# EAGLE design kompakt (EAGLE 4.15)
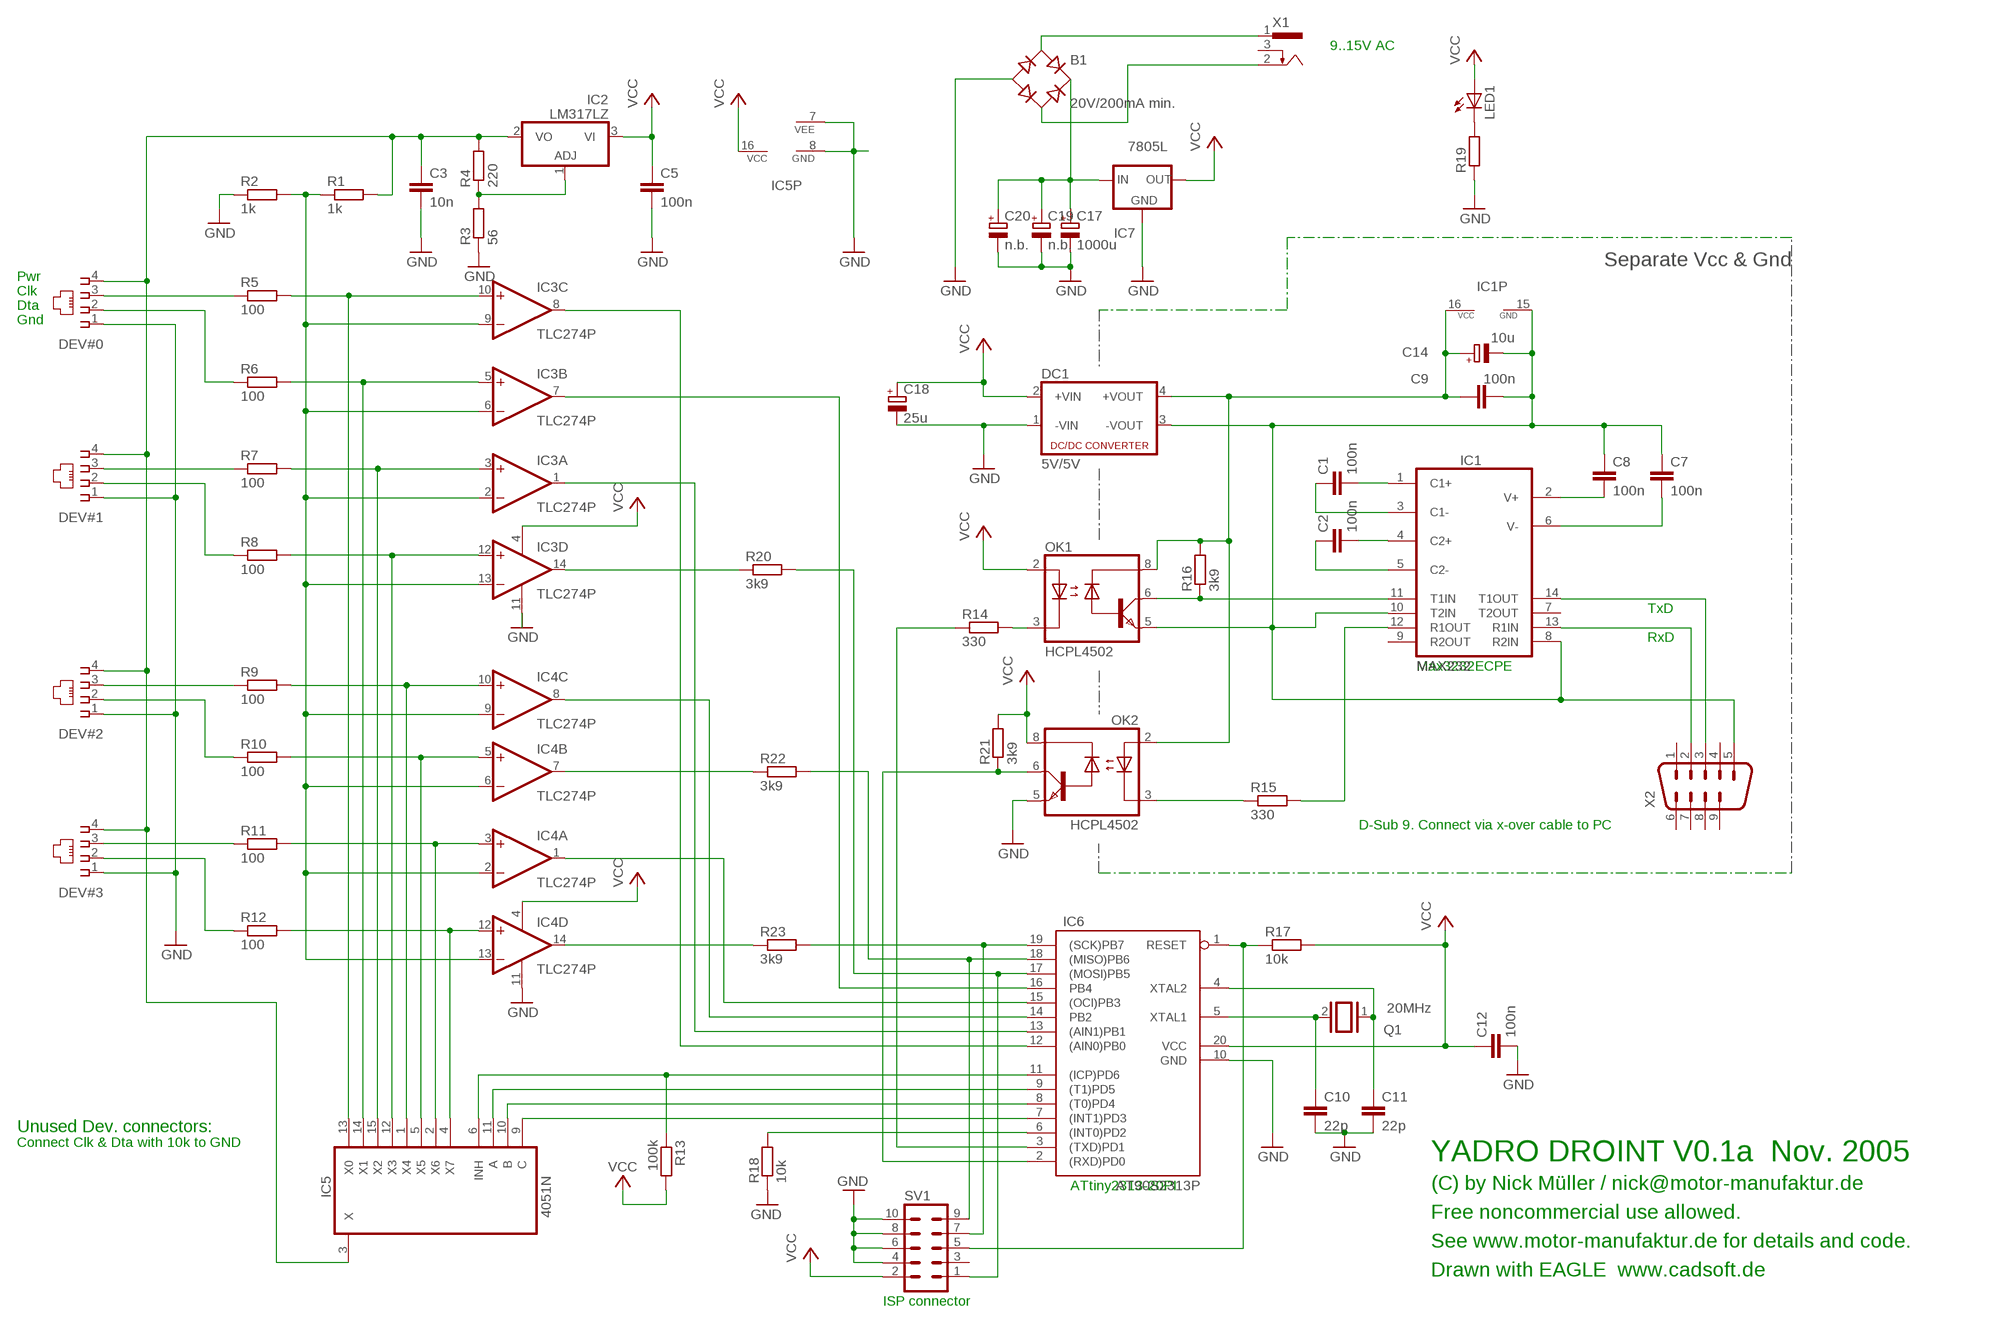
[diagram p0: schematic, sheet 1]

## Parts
B1  20V/200mA min.  RB1A  [RB1A]
C1  100n  C-EU050-030X075  [C050-030X075]
C2  100n  C-EU050-030X075  [C050-030X075]
C3  10n  C-EU025-025X050  [C025-025X050]
C5  100n  C-EU050-030X075  [C050-030X075]
C7  100n  C-EU050-030X075  [C050-030X075]
C8  100n  C-EU050-030X075  [C050-030X075]
C9  100n  C-EU050-030X075  [C050-030X075]
C10  22p  C-EU025-025X050  [C025-025X050]
C11  22p  C-EU025-025X050  [C025-025X050]
C12  100n  C-EU050-030X075  [C050-030X075]
C14  10u  CPOL-EUE5-5  [E5-5]
C17  1000u  CPOL-EUE5-13  [E5-13]
C18  25u  CPOL-EUE5-8.5  [E5-8,5]
C19  n.b.  CPOL-EUE5-10.5  [E5-10,5]
C20  n.b.  CPOL-EUE5-10.5  [E5-10,5]
DC1  5V/5V  NME  [NME]
DEV#0  215876-6  [215876-6]
DEV#1  215876-6  [215876-6]
DEV#2  215876-6  [215876-6]
DEV#3  215876-6  [215876-6]
IC1  MAX232  [DIL16]
IC2  LM317LZ  [TO92]
IC3  TLC274P  [DIL14]
IC4  TLC274P  [DIL14]
IC5  4051N  [DIL16]
IC6  AT90S2313P  [DIL20]
IC7  7805L  78XXL  [78XXL]
LED1  LED3MM  [LED3MM]
OK1  HCPL4502  [DIL08]
OK2  HCPL4502  [DIL08]
Q1  20MHz  XTAL/S  [QS]
R1  1k  R-EU_0207/7  [0207/7]
R2  1k  R-EU_0207/7  [0207/7]
R3  56  R-EU_0207/7  [0207/7]
R4  220  R-EU_0207/7  [0207/7]
R5  100  R-EU_0207/7  [0207/7]
R6  100  R-EU_0207/7  [0207/7]
R7  100  R-EU_0207/7  [0207/7]
R8  100  R-EU_0207/7  [0207/7]
R9  100  R-EU_0207/7  [0207/7]
R10  100  R-EU_0207/7  [0207/7]
R11  100  R-EU_0207/7  [0207/7]
R12  100  R-EU_0207/7  [0207/7]
R13  100k  R-EU_0207/7  [0207/7]
R14  330  R-EU_0207/7  [0207/7]
R15  330  R-EU_0207/7  [0207/7]
R16  3k9  R-EU_0207/7  [0207/7]
R17  10k  R-EU_0207/7  [0207/7]
R18  10k  R-EU_0207/7  [0207/7]
R19  R-EU_0207/7  [0207/7]
R20  3k9  R-EU_0207/7  [0207/7]
R21  3k9  R-EU_0207/7  [0207/7]
R22  3k9  R-EU_0207/7  [0207/7]
R23  3k9  R-EU_0207/7  [0207/7]
SV1  MA05-2  [MA05-2]
X1  SCD-014A  [SCD-014-A]
X2  M09H  [M09H]

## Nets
1.5V: C3.1 DEV#0.4 DEV#1.4 DEV#2.4 DEV#3.4 IC2.2(VO) IC5.3(X) R1.2 R4.2
+5V_ISO: C9.1 C14.+ DC1.4(+VOUT) IC1.16(VCC) OK1.8(VCC) OK2.2(A) R16.2
GND: B1.- C3.2 C5.2 C10.2 C11.2 C12.2 C17.- C18.- C19.- C20.- DC1.1(-VIN) DEV#0.1 DEV#1.1 DEV#2.1 DEV#3.1 IC3.11(P:V-) IC4.11(P:V-) IC5.7(VEE) IC5.8(GND) IC6.10(GND) IC7.GND OK2.5(GND) R2.1 R3.1 R18.1 R19.1 SV1.4 SV1.6 SV1.8 SV1.10
GND_ISO: C7.1 C8.1 C9.2 C14.- DC1.3(-VOUT) IC1.8(R2IN) IC1.10(T2IN) IC1.15(GND) OK1.5(GND) X2.5
N$2: DEV#3.2 R12.1
N$3: DEV#0.2 R6.1
N$4: DEV#3.3 R11.1
N$5: DEV#1.2 R8.1
N$6: DEV#2.3 R9.1
N$7: DEV#2.2 R10.1
N$8: DEV#1.3 R7.1
N$9: DEV#0.3 R5.1
N$10: IC3.5(B:+IN) IC5.14(X1) R6.2
N$11: IC3.10(C:+IN) IC5.13(X0) R5.2
N$12: IC3.3(A:+IN) IC5.15(X2) R7.2
N$13: IC3.14(D:OUT) R20.1
N$14: IC2.1(ADJ) R3.2 R4.1
N$15: IC3.12(D:+IN) IC5.12(X3) R8.2
N$16: IC4.10(C:+IN) IC5.1(X4) R9.2
N$17: IC4.5(B:+IN) IC5.5(X5) R10.2
N$18: IC4.3(A:+IN) IC5.2(X6) R11.2
N$19: IC4.12(D:+IN) IC5.4(X7) R12.2
N$20: C1.2 IC1.1(C1+)
N$21: IC5.9(C) IC6.7((INT1)PD3)
N$22: IC5.10(B) IC6.8((T0)PD4)
N$23: IC5.11(A) IC6.9((T1)PD5)
N$24: B1.+ C17.+ C19.+ C20.+ IC7.IN
N$25: C11.1 IC6.4(XTAL2) Q1.1
N$26: C10.1 IC6.5(XTAL1) Q1.2
N$27: IC3.8(C:OUT) IC6.12((AIN0)PB0)
N$28: IC3.1(A:OUT) IC6.13((AIN1)PB1)
N$29: IC4.8(C:OUT) IC6.14(PB2)
N$30: IC4.1(A:OUT) IC6.15((OCI)PB3)
N$31: IC3.7(B:OUT) IC6.16(PB4)
N$32: IC6.17((MOSI)PB5) R20.2 SV1.1
N$33: C1.1 IC1.3(C1-)
N$34: IC6.18((MISO)PB6) R22.2 SV1.9
N$35: IC6.19((SCK)PB7) R23.2 SV1.7
N$36: C2.2 IC1.4(C2+)
N$37: C2.1 IC1.5(C2-)
N$38: IC1.14(T1OUT) X2.3
N$39: IC6.3((TXD)PD1) R14.1
N$40: IC1.13(R1IN) X2.2
N$42: IC1.12(R1OUT) R15.2
N$43: OK1.3(C) R14.2
N$44: IC1.11(T1IN) OK1.6(VO) R16.1
N$45: IC5.6(INH) IC6.11((ICP)PD6) R13.1
N$46: B1.AC1 X1.1
N$47: IC6.6((INT0)PD2) R18.2
N$49: C8.2 IC1.2(V+)
N$50: C7.2 IC1.6(V-)
N$51: IC6.1(RESET) R17.1 SV1.5
N$53: OK2.3(C) R15.1
N$54: IC4.7(B:OUT) R22.1
N$55: B1.AC2 X1.2
N$56: LED1.K(C) R19.2
N$57: IC4.14(D:OUT) R23.1
N$58: IC6.2((RXD)PD0) OK2.6(VO) R21.1
VCC: C5.1 C12.1 C18.+ DC1.2(+VIN) IC2.3(VI) IC3.4(P:V+) IC4.4(P:V+) IC5.16(VCC) IC6.20(VCC) IC7.OUT LED1.A OK1.2(A) OK2.8(VCC) R13.2 R17.2 R21.2 SV1.2
VREF: IC3.2(A:-IN) IC3.6(B:-IN) IC3.9(C:-IN) IC3.13(D:-IN) IC4.2(A:-IN) IC4.6(B:-IN) IC4.9(C:-IN) IC4.13(D:-IN) R1.1 R2.2
Unconnected: IC1.7(T2OUT) IC1.9(R2OUT) SV1.3 X1.3 X2.1 X2.4 X2.6 X2.7 X2.8 X2.9

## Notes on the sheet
- 9..15V AC
- Separate Vcc & Gnd
- Pwr
- Clk
- Dta
- Gnd
- TxD
- RxD
- Max3232ECPE
- D-Sub 9. Connect via x-over cable to PC
- Unused Dev. connectors:
- Connect Clk & Dta with 10k to GND
- YADRO DROINT V0.1a  Nov. 2005
- ATtiny2313-20PI | (C) by Nick Müller / nick@motor-manufaktur.de
- Free noncommercial use allowed.
- See www.motor-manufaktur.de for details and code.
- Drawn with EAGLE  www.cadsoft.de
- ISP connector

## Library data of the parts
B1 = rectifier:RB1A: RECTIFIER 1 A
C1-C3 C5 C7-C12 = rcl:C-EU: CAPACITOR, European symbol
C14 C17-C20 = rcl:CPOL-EU: POLARIZED CAPACITOR, European symbol
DC1 = dc-dc-converter:NME: DC-DC CONVERTER
DEV#0 DEV#1-DEV#3 = con-amp:215876-6: AMP connector
IC1 = maxim:MAX232: RS232 TRANSEIVER
IC2 = linear:*317: Positive VOLTAGE REGULATOR
IC3 IC4 = linear:TLC274: OP AMP
IC5 = 40xx:4051: 8-channel ANALOG MULTIPLEXER
IC6 = atmel:AT90S2313: MICROCONTROLLER 2 Kbytes FLASH 128 bytes SRAM 128 bytes EEPROM UART
IC7 = v-reg:78XXL: VOLTAGE REGULATOR
LED1 = led:LED: LED
OK1 OK2 = optocoupler:HCPL4502: HEWLETT PACKARD OPTO COUPLER
Q1 = special:XTAL/S: CRYSTAL
R1-R23 = rcl:R-EU_: RESISTOR, European symbol
SV1 = con-lstb:MA05-2: PIN HEADER
X1 = con-shiua-chyuan:SCD-014A: Power Jack 2.5mm
X2 = con-subd:M09: SUB-D

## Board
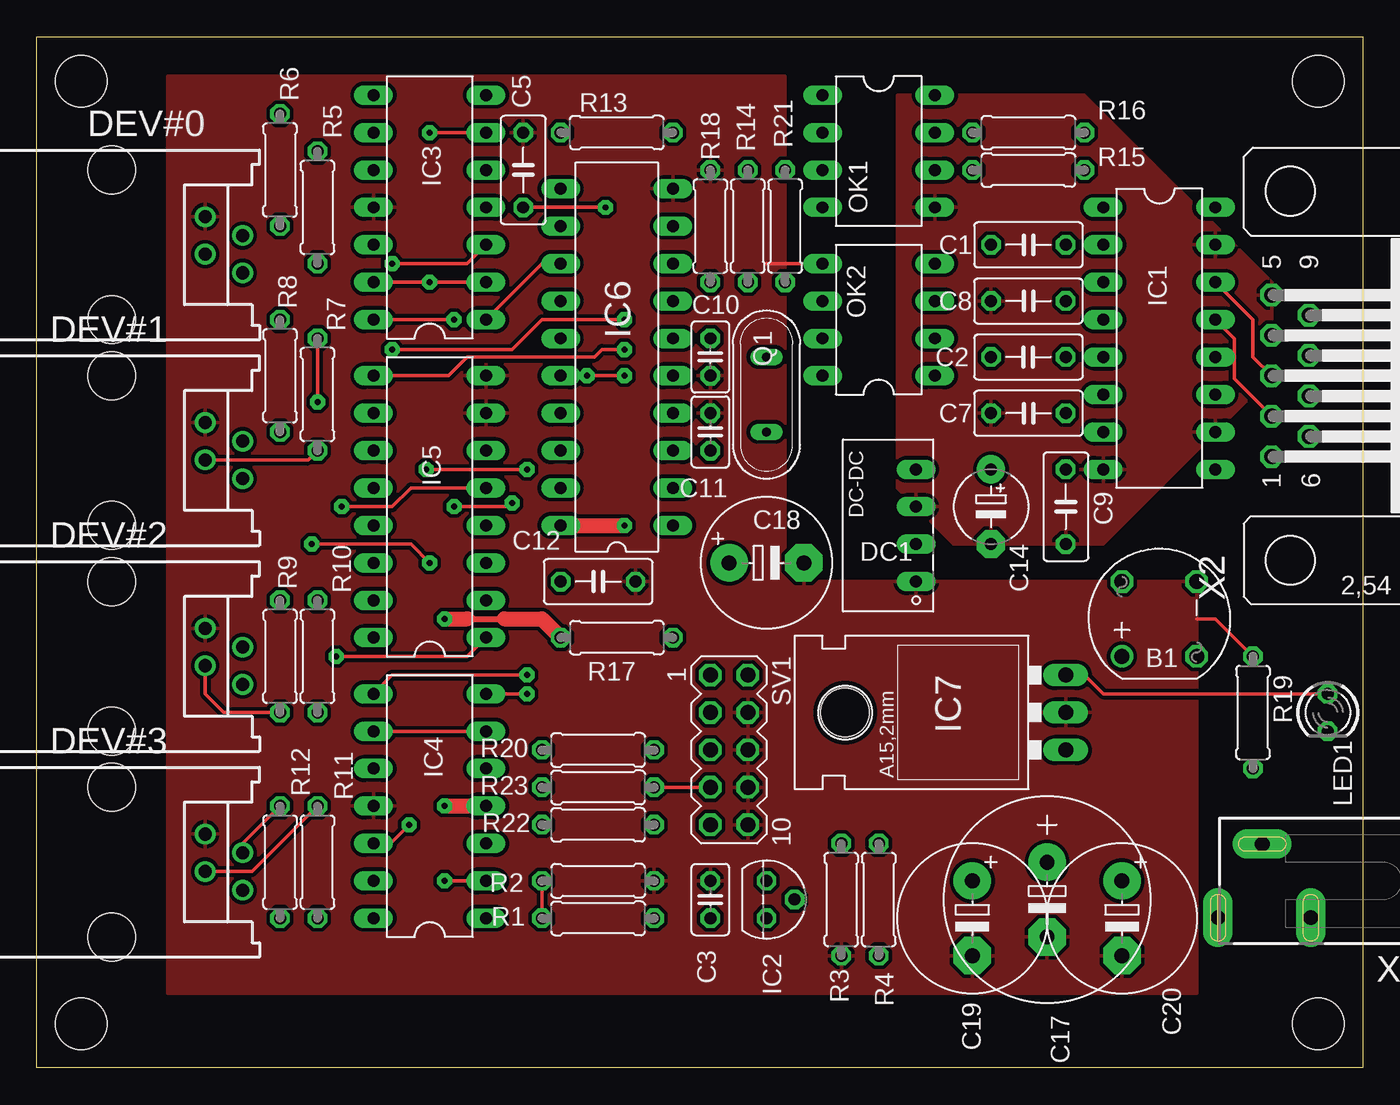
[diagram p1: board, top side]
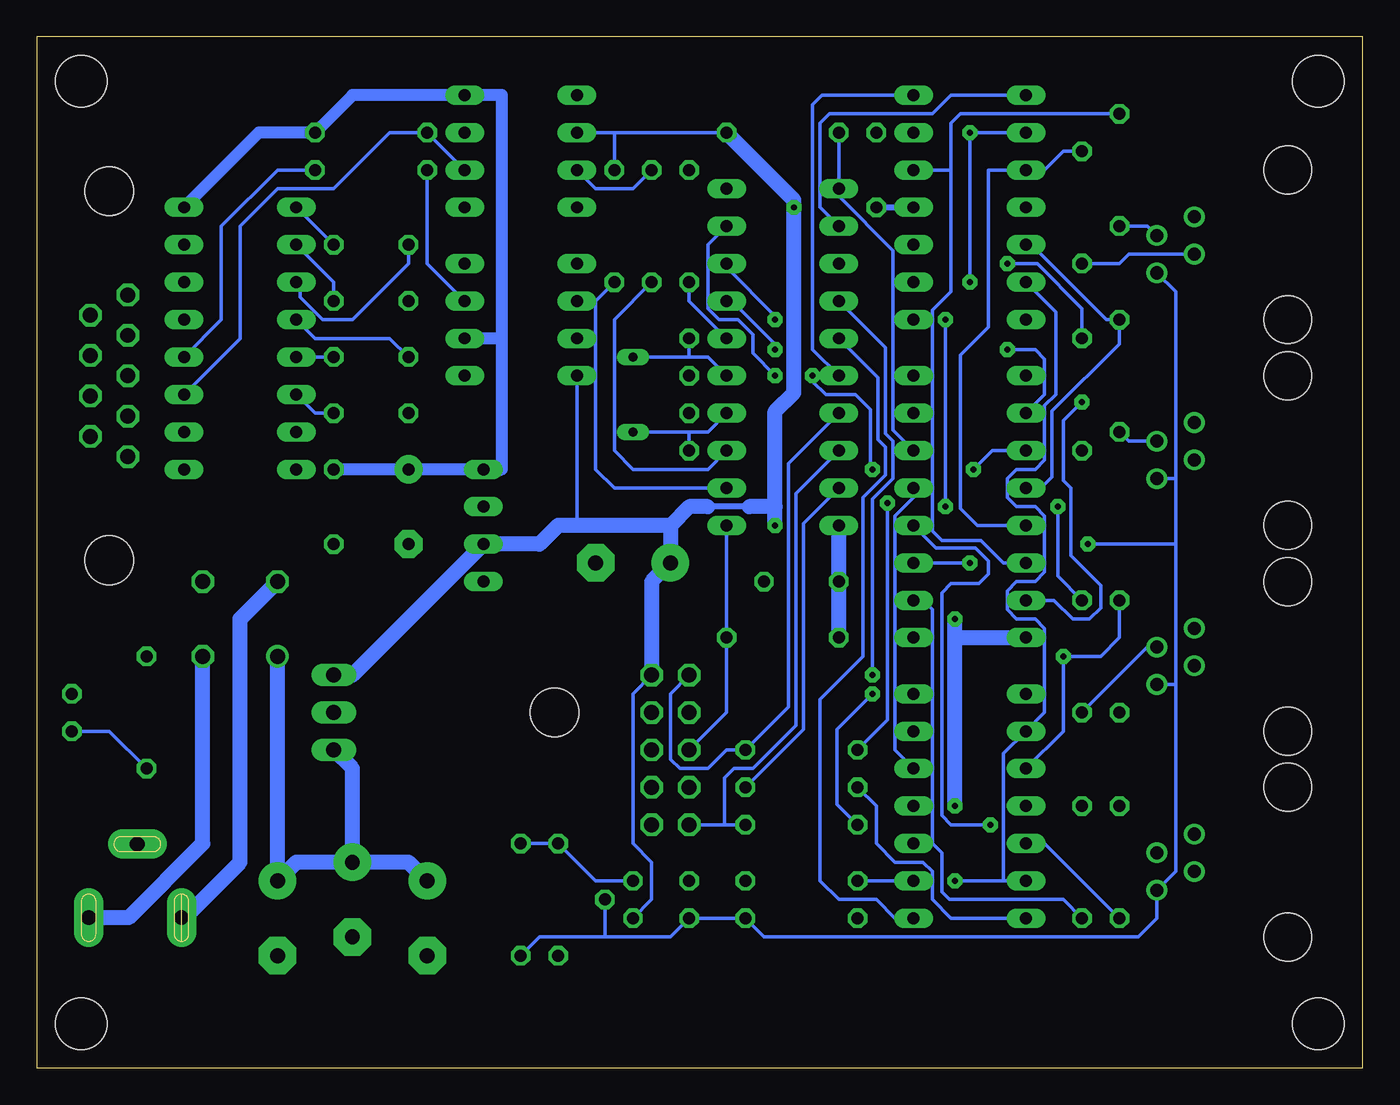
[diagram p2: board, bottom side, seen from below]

Size 90 x 70 mm. Coordinates in mm from the lower left corner, seen from the top.
Outline: 0,70 90,70 90,0 0,0 0,70
Copper layers (1*16): Top 0.035mm / dielectric 1.5mm / Bottom 0.035mm
Design rules "10mil": minimum track width 10mil, minimum drill 16mil, track to track 10mil, track to pad 15mil, pad to pad 20mil, via to via 10mil, smd to smd 8mil, copper to edge 20mil, drill to drill 8mil, minimum pad ring 10mil, minimum via ring 8mil, stop-mask expansion 4mil, vias tented up to drill 16mil, thermal gap 10mil
Holes 3.5 mm at 3,3 3,67 87,67 87,3
tKeepout: area 0,0 to 6,6; area 0,64 to 6,70; area 84,64 to 90,70; area 84,0 to 90,6

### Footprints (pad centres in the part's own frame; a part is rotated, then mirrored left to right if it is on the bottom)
RB1A = drill 1.016 round: + -2.54,2.54 | drill 1.016 octagon: - 2.54,-2.54; AC1 2.54,2.54; AC2 -2.54,-2.54
C050-030X075 = drill 0.813 octagon: 1 -2.54,0; 2 2.54,0
C025-025X050 = drill 0.813 octagon: 1 -1.27,0; 2 1.27,0
E5-5 = drill 0.813 pad 1.905 round: + -2.54,0 | drill 0.813 pad 1.905 octagon: - 2.54,0
E5-13 = drill 1.016 pad 2.54 round: + -2.54,0 | drill 1.016 pad 2.54 octagon: - 2.54,0
E5-8,5 = drill 1.016 pad 2.54 round: + -2.54,0 | drill 1.016 pad 2.54 octagon: - 2.54,0
E5-10,5 = drill 1.016 pad 2.54 round: + -2.54,0 | drill 1.016 pad 2.54 octagon: - 2.54,0
NME = drill 0.813 long: 1 0,3.81; 2 0,1.27; 3 0,-1.27; 4 0,-3.81
215876-6 = drill 0.889 round: 1 -1.905,6.35; 2 -0.635,8.89; 3 0.635,6.35; 4 1.905,8.89 | hole 3.251: -5.08,0; 5.08,0
DIL16 = drill 0.813 long: 1 -8.89,-3.81; 2 -6.35,-3.81; 3 -3.81,-3.81; 4 -1.27,-3.81; 5 1.27,-3.81; 6 3.81,-3.81; 7 6.35,-3.81; 8 8.89,-3.81; 9 8.89,3.81; 10 6.35,3.81; 11 3.81,3.81; 12 1.27,3.81; 13 -1.27,3.81; 14 -3.81,3.81; 15 -6.35,3.81; 16 -8.89,3.81
TO92 = drill 0.813 octagon: 1 -1.27,0; 2 0,1.905; 3 1.27,0
DIL14 = drill 0.813 long: 1 -7.62,-3.81; 2 -5.08,-3.81; 3 -2.54,-3.81; 4 0,-3.81; 5 2.54,-3.81; 6 5.08,-3.81; 7 7.62,-3.81; 8 7.62,3.81; 9 5.08,3.81; 10 2.54,3.81; 11 0,3.81; 12 -2.54,3.81; 13 -5.08,3.81; 14 -7.62,3.81
DIL20 = drill 0.813 long: 1 -11.43,-3.81; 2 -8.89,-3.81; 3 -6.35,-3.81; 4 -3.81,-3.81; 5 -1.27,-3.81; 6 1.27,-3.81; 7 3.81,-3.81; 8 6.35,-3.81; 9 8.89,-3.81; 10 11.43,-3.81; 11 11.43,3.81; 12 8.89,3.81; 13 6.35,3.81; 14 3.81,3.81; 15 1.27,3.81; 16 -1.27,3.81; 17 -3.81,3.81; 18 -6.35,3.81; 19 -8.89,3.81; 20 -11.43,3.81
78XXL = drill 1.016 long: GND 0,-3.81; IN -2.54,-3.81; OUT 2.54,-3.81 | hole 3.302: 0,11.176
LED3MM = drill 0.813 octagon: A -1.27,0; K 1.27,0
DIL08 = drill 0.813 long: 1 -3.81,-3.81; 2 -1.27,-3.81; 3 1.27,-3.81; 4 3.81,-3.81; 5 3.81,3.81; 6 1.27,3.81; 7 -1.27,3.81; 8 -3.81,3.81
QS = drill 0.61 long: 1 -2.54,0; 2 2.54,0
0207/7 = drill 0.813 octagon: 1 -3.81,0; 2 3.81,0
MA05-2 = drill 1.016 octagon: 1 -5.08,-1.27; 2 -5.08,1.27; 3 -2.54,-1.27; 4 -2.54,1.27; 5 0,-1.27; 6 0,1.27; 7 2.54,-1.27; 8 2.54,1.27; 9 5.08,-1.27; 10 5.08,1.27
SCD-014-A = drill 1 pad 2 long: 1 -2.5,13.8; 2 -2.5,7.5; 3 2.5,10.8
M09H = drill 1.016 octagon: 1 -5.486,1.27; 2 -2.743,1.27; 3 0,1.27; 4 2.743,1.27; 5 5.486,1.27; 6 -4.115,-1.27; 7 -1.372,-1.27; 8 1.372,-1.27; 9 4.115,-1.27 | hole 3.302: 12.522,0; -12.522,0

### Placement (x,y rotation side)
B1  76.2,30.48 90 top
C1  67.31,55.88 0 top
C2  67.31,48.26 180 top
C3  45.72,11.43 90 top
C5  33.02,60.96 90 top
C7  67.31,44.45 0 top
C8  67.31,52.07 0 top
C9  69.85,38.1 270 top
C10  45.72,48.26 270 top
C11  45.72,43.18 90 top
C12  38.1,33.02 0 top
C14  64.77,38.1 270 top
C17  68.58,11.43 270 top
C18  49.53,34.29 0 top
C19  63.5,10.16 270 top
C20  73.66,10.16 270 top
DC1  59.69,36.83 180 top
DEV#0  5.08,55.88 270 top
DEV#1  5.08,41.91 270 top
DEV#2  5.08,27.94 270 top
DEV#3  5.08,13.97 270 top
IC1  76.2,49.53 270 top
IC2  49.53,11.43 270 top
IC3  26.67,58.42 90 top
IC4  26.67,17.78 90 top
IC5  26.67,38.1 90 top
IC6  39.37,48.26 90 top
IC7  66.04,24.13 90 top
LED1  87.63,24.13 270 top
OK1  57.15,62.23 270 top
OK2  57.15,50.8 90 top
Q1  49.53,45.72 90 top
R1  38.1,10.16 0 top
R2  38.1,12.7 180 top
R3  54.61,11.43 90 top
R4  57.15,11.43 270 top
R5  19.05,58.42 90 top
R6  16.51,60.96 90 top
R7  19.05,45.72 90 top
R8  16.51,46.99 90 top
R9  16.51,27.94 90 top
R10  19.05,27.94 90 top
R11  19.05,13.97 270 top
R12  16.51,13.97 270 top
R13  39.37,63.5 0 top
R14  48.26,57.15 90 top
R15  67.31,60.96 0 top
R16  67.31,63.5 0 top
R17  39.37,29.21 180 top
R18  45.72,57.15 270 top
R19  82.55,24.13 270 top
R20  38.1,21.59 0 top
R21  50.8,57.15 90 top
R22  38.1,16.51 0 top
R23  38.1,19.05 0 top
SV1  46.99,21.59 270 top
X1  93.98,12.7 90 top
X2  85.09,46.99 90 top

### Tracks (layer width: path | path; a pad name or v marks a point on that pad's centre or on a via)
1.5V  (via drill 0.41 pad 1.02)
  Top 0.254: v26.67,34.29 25.4,35.56 v18.67,35.56
  Bottom 0.254: v26.67,34.29 IC5.3 | 12.7,35.56 v18.67,35.56 | DEV#0.4 12.7,52.7 12.7,40.01 | 12.7,26.04 12.7,35.56 | 12.7,35.56 12.7,40.01 | 12.7,40.01 DEV#1.4 | 12.7,26.04 DEV#2.4 | 12.7,26.04 12.7,13.34 DEV#3.4 13.97,10.16 15.24,8.89 40.64,8.89 R1.2 C3.1 46.99,8.89 51.44,8.89 | R4.2 55.88,8.89 51.44,8.89 | 51.44,8.89 IC2.2
+5V_ISO
  Bottom 0.813: 58.42,49.53 58.42,66.04 OK1.8 68.58,66.04 R16.2 74.93,63.5 IC1.16 | 58.42,49.53 OK2.2 | 58.42,49.53 58.42,40.64 DC1.4 C14.+ C9.1
GND
  Top 0.254: R19.1 80.01,30.48 78.74,30.48 | 49.53,54.61 OK2.5
  pour Top: 8.89,67.31 50.8,67.31 50.8,34.29 52.07,34.29 52.07,33.02 78.74,33.02 78.74,5.08 8.89,5.08
GND_ISO
  pour Top: 83.82,53.34 71.12,66.04 58.42,66.04 58.42,39.37 62.23,35.56 72.39,35.56 83.82,46.99
N$2
  Top 0.254: DEV#3.2 13.97,15.24 R12.1
N$3
  Bottom 0.254: DEV#0.2 14.61,57.15 R6.1
N$4
  Top 0.254: DEV#3.3 14.61,13.34 R11.1
N$5
  Bottom 0.254: DEV#1.2 15.88,42.55 R8.1
N$6
  Top 0.254: DEV#2.3 11.43,25.4 12.7,24.13 R9.1
N$7
  Bottom 0.254: DEV#2.2 14.61,28.57 R10.1
N$8
  Top 0.254: DEV#1.3 18.41,41.27 R7.1
N$9
  Bottom 0.254: DEV#0.3 15.88,55.24 16.51,54.61 R5.1
N$10
  Bottom 0.254: 27.94,60.96 IC3.5 | 27.94,60.96 27.94,52.7 29.21,51.44 29.21,36.45 28.57,35.81 25.91,35.81 24.38,34.29 IC5.14 | 27.94,60.96 27.94,64.14 27.3,64.77 R6.2
N$11
  Bottom 0.254: IC5.13 26.16,36.83 27.3,37.97 27.3,48.39 25.4,50.29 25.4,60.96 IC3.10 21.59,60.96 20.32,62.23 R5.2
N$12  (via drill 0.41 pad 1.02)
  Top 0.254: IC3.3 29.21,54.61 v24.13,54.61 | v19.05,45.21 R7.2
  Bottom 0.254: IC5.15 20.95,31.75 19.68,30.48 18.54,30.48 17.78,31.24 17.78,32.77 19.81,34.8 19.81,39.37 20.32,39.88 20.32,43.94 v19.05,45.21 | v24.13,54.61 22.1,54.61 19.05,51.56 R7.2
N$13  (via drill 0.41 pad 1.02)
  Top 0.254: v28.32,50.8 IC3.14 | v28.32,38.1 32.26,38.1 v32.26,38.35
  Bottom 0.254: v28.32,38.1 v28.32,50.8 | v32.26,38.35 32.26,23.62 R20.1
N$14
  Bottom 0.254: IC2.1 52.07,12.7 R3.2 R4.1
N$15
  Bottom 0.254: IC5.12 21.84,39.37 21.08,40.13 21.08,44.58 16.51,49.15 R8.2 17.4,50.8 22.48,55.88 IC3.12
N$16  (via drill 0.41 pad 1.02)
  Top 0.254: IC5.1 29.21,27.94 v20.32,27.94
  Bottom 0.254: IC4.10 20.32,22.86 v20.32,27.94 17.78,27.94 16.51,29.21 R9.2
N$17  (via drill 0.41 pad 1.02)
  Top 0.254: IC5.5 25.4,39.37 24.13,38.1 v20.7,38.1
  Bottom 0.254: IC5.5 30.48,38.73 31.75,37.47 31.75,21.59 IC4.5 | R10.2 20.7,33.4 v20.7,38.1
N$18
  Bottom 0.254: 29.21,15.24 29.21,31.11 29.84,31.75 IC5.2 | 29.21,15.24 IC4.3 | R11.2 20.32,11.43 28.07,11.43 28.57,11.94 28.57,14.61 29.21,15.24
N$19  (via drill 0.41 pad 1.02)
  Top 0.254: v25.27,16.51 24,15.24 IC4.12
  Bottom 0.254: v25.27,16.51 27.94,16.51 28.57,17.14 28.57,32.26 27.94,32.89 26.04,32.89 25.4,33.53 25.4,34.42 26.29,35.31 28.96,35.31 IC5.4 | IC4.12 21.59,15.24 R12.2
N$20
  Bottom 0.254: C1.2 IC1.1
N$21  (via drill 0.41 pad 1.02)
  Top 0.254: v39.88,48.77 38.35,48.77 37.85,48.26 29.21,48.26 27.94,46.99 IC5.9
  Bottom 0.254: v39.88,48.77 39.88,49.15 42.8,52.07 IC6.7
N$22  (via drill 0.41 pad 1.02)
  Top 0.254: v24.13,48.77 32.26,48.77 34.29,50.8 v39.88,50.8
  Bottom 0.254: IC5.10 21.59,45.72 21.59,48.13 22.23,48.77 v24.13,48.77 | v39.88,50.8 39.88,51.05 43.18,54.36 IC6.8
N$23  (via drill 0.41 pad 1.02)
  Top 0.254: v26.42,40.64 v33.27,40.64 | v37.34,46.99 v39.88,46.99
  Bottom 0.254: IC6.9 44.45,55.88 44.45,51.56 43.69,50.8 42.42,50.8 41.4,49.78 41.4,48.51 v39.88,46.99 | v33.27,40.64 33.4,40.64 33.4,44.7 34.42,45.72 36.45,45.72 37.34,46.61 v37.34,46.99 | IC5.11 25.15,41.91 v26.42,40.64
N$24
  Bottom 1.016: B1.+ C20.+ 72.39,13.97 C17.+ | C17.+ 64.77,13.97 C19.+ | IC7.IN 68.58,20.32 C17.+
N$25
  Bottom 0.254: IC6.4 44.45,43.18 45.72,43.18 | C11.1 45.72,43.18 | 45.72,43.18 Q1.1
N$26
  Bottom 0.254: IC6.5 44.45,48.26 45.72,48.26 | 45.72,48.26 C10.1 | 45.72,48.26 Q1.2
N$27
  Bottom 0.254: IC6.12 36.83,58.42 36.83,64.14 36.2,64.77 29.21,64.77 27.94,66.04 IC3.8
N$28
  Top 0.254: IC6.13 34.29,54.61 IC3.1
N$29  (via drill 0.41 pad 1.02)
  Top 0.254: IC4.8 24.13,26.67 v33.27,26.67
  Bottom 0.254: IC6.14 32.38,48.9 32.38,43.05 31.88,42.55 31.88,40.01 33.27,38.61 v33.27,26.67
N$30
  Bottom 0.254: IC6.15 32.89,46.86 32.89,42.67 32.38,42.16 32.38,40.26 33.91,38.73 33.91,27.94 36.83,25.02 36.83,12.7 35.56,11.43 33.02,11.43 31.75,10.16 IC4.1
N$31
  Bottom 0.254: IC6.16 37.34,48.77 37.34,65.41 36.7,66.04 IC3.7
N$32
  Bottom 0.254: IC6.17 38.99,41.02 38.99,24.51 R20.2 43.18,21.59 44.45,20.32 46.35,20.32 46.99,20.95 46.99,25.4 SV1.1
N$33
  Bottom 0.254: C1.1 64.77,54.61 68.58,50.8 70.61,50.8 72.14,52.32 72.14,53.34 IC1.3
N$34
  Bottom 0.254: IC6.18 38.48,38.99 38.48,23.24 41.4,20.32 42.67,20.32 43.31,19.68 43.31,16.51 | R22.2 43.31,16.51 | 43.31,16.51 SV1.9
N$35
  Top 0.254: R23.2 SV1.7
  Bottom 0.254: IC6.19 37.97,36.96 37.97,35.94 37.97,22.99 R23.2
N$36
  Bottom 0.254: C2.2 66.04,49.53 71.12,49.53 IC1.4
N$37
  Bottom 0.254: C2.1 IC1.5
N$38
  Top 0.254: X2.3 82.55,48.26 82.55,50.8 IC1.14
N$39
  Bottom 0.254: IC6.3 44.45,40.64 49.53,40.64 50.8,41.91 50.8,50.8 R14.1
N$40
  Top 0.254: X2.2 81.28,46.79 81.28,49.53 IC1.13
N$42
  Bottom 0.254: R15.2 73.66,60.96 77.47,57.15 77.47,50.8 IC1.12
N$43
  Bottom 0.254: R14.2 49.53,59.69 52.07,59.69 OK1.3
N$44
  Bottom 0.254: OK1.6 R16.1 66.04,63.5 69.85,59.69 73.66,59.69 76.2,57.15 76.2,49.53 IC1.11
N$45
  Bottom 0.254: IC5.6 31.88,43.31 31.88,55.5 35.56,59.18 IC6.11 R13.1
N$46
  Bottom 1.016: B1.AC1 76.2,30.48 76.2,13.97 80.01,10.16 80.05,10.2 X1.1
N$47
  Bottom 0.254: R18.2 45.72,52.07 IC6.6
N$49
  Bottom 0.254: C8.2 69.85,53.34 IC1.2
N$50
  Bottom 0.254: C7.2 71.12,44.45 IC1.6
N$51
  Bottom 0.254: IC6.1 R17.1 43.18,24.13 SV1.5
N$53
  Bottom 0.254: OK2.3 63.5,54.61 R15.1
N$54  (via drill 0.41 pad 1.02)
  Top 0.254: v33.27,25.4 IC4.7
  Bottom 0.254: v33.27,25.4 35.69,22.99 35.69,17.91 R22.1
N$55
  Bottom 1.016: X1.2 83.78,10.2 78.74,15.24 B1.AC2
N$56
  Bottom 0.254: LED1.K 85.09,22.86 R19.2
N$57
  Bottom 0.254: IC4.14 27.94,10.16 29.21,11.43 29.21,13.34 29.84,13.97 31.75,13.97 33.02,15.24 33.02,17.78 R23.1
N$58
  Bottom 0.254: 52.07,52.07 R21.1 | 52.07,52.07 52.07,40.64 50.8,39.37 IC6.2 | 52.07,52.07 OK2.6
VCC  (via drill 0.41 pad 1.02)
  Top 0.254: v38.61,58.42 C5.1 | IC7.OUT 71.12,26.67 72.39,25.4 LED1.A
  Top 0.406: 29.21,30.48 31.75,30.48
  Top 1.016: v27.69,17.78 IC4.4 | v27.69,30.48 29.21,30.48 | 31.75,30.48 34.29,30.48 R17.2 | IC6.20 v39.88,36.83
  Bottom 0.254: R13.2 50.8,63.5 | 50.8,63.5 R21.2 | SV1.2 49.53,25.4 49.53,15.24 48.26,13.97 48.26,11.43 IC2.3 | 50.8,63.5 OK1.2 | 53.34,36.83 OK2.8
  Bottom 0.406: 41.66,38.1 44.45,38.1 | C5.1 IC3.4
  Bottom 1.016: R13.2 38.61,58.93 v38.61,58.42 38.61,45.85 39.88,44.58 39.88,38.1 | v27.69,17.78 27.69,29.21 | 27.69,29.21 IC5.16 | 27.69,29.21 v27.69,30.48 | v39.88,36.83 39.88,38.1 | IC6.20 C12.1 R17.2 | 44.45,38.1 45.72,38.1 46.99,36.83 | 46.99,36.83 53.34,36.83 54.61,36.83 55.88,35.56 DC1.2 68.58,26.67 IC7.OUT | 39.88,38.1 41.66,38.1 | 46.99,36.83 C18.+ 48.26,33.02 SV1.2
VREF  (via drill 0.41 pad 1.02)
  Top 0.254: v27.69,12.7 IC4.2 | IC4.9 IC4.6 | v26.67,63.5 IC3.6 | IC3.13 v26.67,53.34 IC3.2 | R2.2 R1.1
  Bottom 0.254: IC4.13 24.38,12.7 | IC3.9 v26.67,63.5 v26.67,53.34 | 24.38,12.7 v27.69,12.7 | 24.38,12.7 24.38,21.34 IC4.9 21.59,24.13 21.59,29.84 22.23,30.48 23.5,30.48 24.13,31.11 24.13,32.38 23.5,33.02 22.23,33.02 21.59,33.66 21.59,37.47 22.23,38.1 23.5,38.1 24.13,38.73 24.13,40.01 23.5,40.64 22.23,40.64 21.59,41.27 21.59,44.96 20.83,45.72 20.83,51.31 IC3.13 | IC4.2 R2.2

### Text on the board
Text: (C) by Nick Müller // www.motor-manufaktur.de | YADRO-DROINT V0.1a PCB0.0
